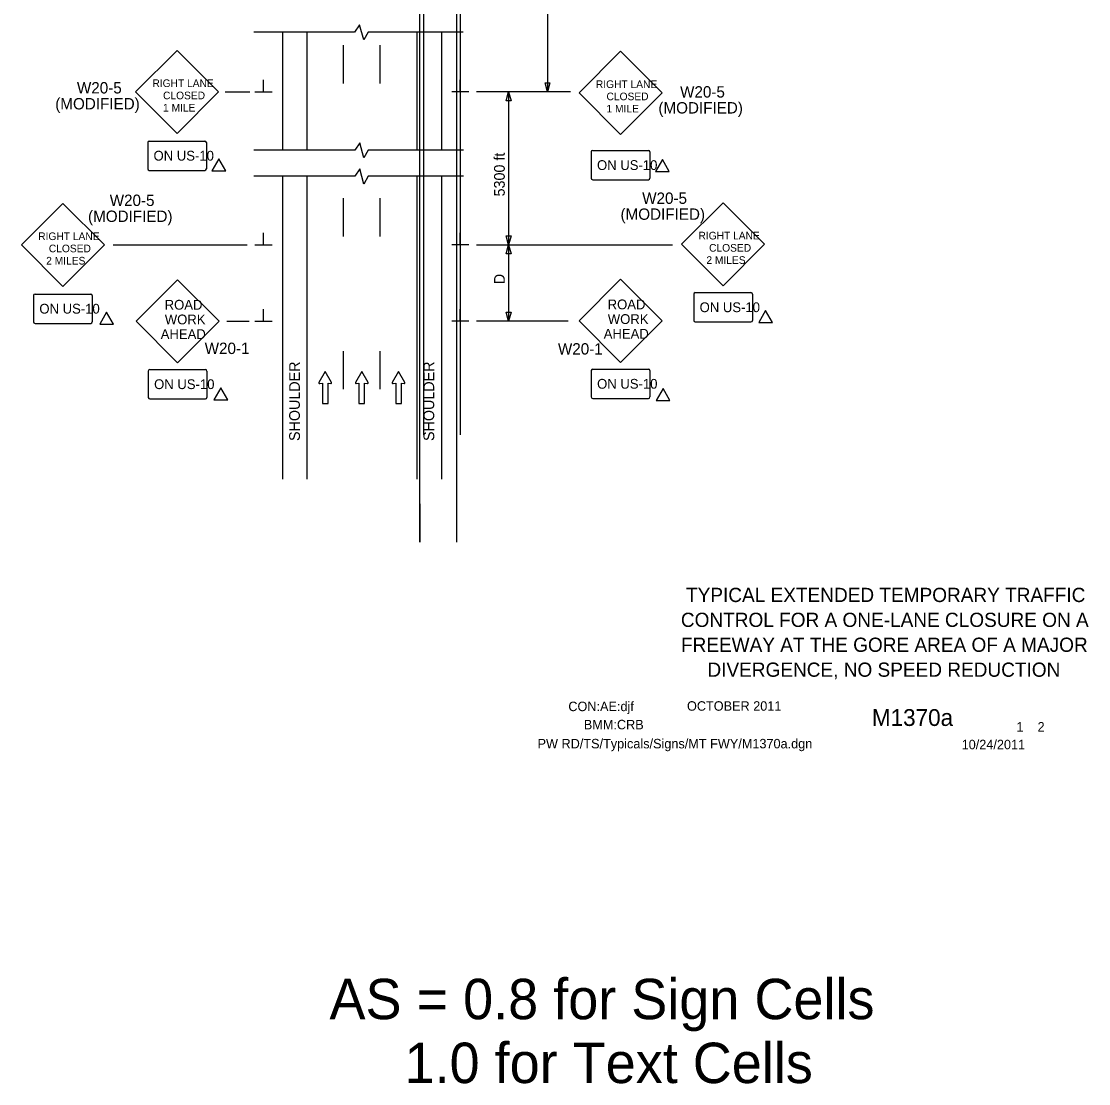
# Model space of a CAD drawing. Extents: x 16722 to 18475, y 7001 to 8243.
# Drawn here: x 16733 to 17431, y 7001 to 7696 of the extents above; entities that cross this region are included whole.
import ezdxf

# ---------------------------------------------------------------- set-up
doc = ezdxf.new("R2010")
doc.units = 0
for name, color, linetype in [('ALI_LEGAL_EX', 7, 'Continuous'), ('BORDER', 7, 'Continuous'), ('BORDER_SIGNAL_WO', 7, 'Continuous'), ('MT_SCRATCH_LEVEL_E', 7, 'Continuous'), ('PAVT_EDGE_EX', 7, 'Continuous'), ('TRAFFIC_SIGNS_PR', 7, 'Continuous'), ('TYPICAL_TEXT_DIMEN_PR', 7, 'Continuous')]:
    doc.layers.add(name, color=color, linetype=linetype)

msp = doc.modelspace()

# ---------------------------------------------------------------- linework, layer by layer
at = {"layer": 'ALI_LEGAL_EX'}
for p, q in [((16995.95, 8243.16), (16995.95, 7425.02)), ((17019.95, 8243.16), (17019.95, 7425.02)), ((16993.65, 7354.84), (16993.65, 7855.19)), ((17017.65, 7354.84), (17017.65, 7855.19))]:
    msp.add_line(p, q, dxfattribs=at)
for points in [[(16943.65, 7654.84), (16943.65, 7679.84)], [(16967.65, 7654.84), (16967.65, 7679.84)], [(16943.65, 7554.84), (16943.65, 7579.84)], [(16967.65, 7554.84), (16967.65, 7579.84)], [(16943.65, 7454.84), (16943.65, 7479.84)], [(16967.65, 7454.84), (16967.65, 7479.84)], [(16993.65, 7379.84), (16993.65, 7354.84)]]:
    msp.add_lwpolyline(points, dxfattribs=at)
at = {"layer": 'MT_SCRATCH_LEVEL_E'}
for p, q in [((16931.67, 7466.47), (16927.55, 7459.23)), ((16935.81, 7459.23), (16931.67, 7466.47)), ((16955.57, 7466.47), (16951.46, 7459.23)), ((16959.72, 7459.23), (16955.57, 7466.47)), ((16979.62, 7466.47), (16975.51, 7459.23)), ((16983.77, 7459.23), (16979.62, 7466.47)), ((16928.04, 7458.54), (16929.81, 7458.86)), ((16929.81, 7458.86), (16929.81, 7445.6)), ((16933.56, 7445.6), (16933.56, 7458.86)), ((16933.56, 7458.86), (16935.33, 7458.54)), ((16951.94, 7458.54), (16953.72, 7458.86)), ((16953.72, 7458.86), (16953.72, 7445.6)), ((16957.46, 7445.6), (16957.46, 7458.86)), ((16957.46, 7458.86), (16959.24, 7458.54)), ((16975.99, 7458.54), (16977.77, 7458.86)), ((16977.77, 7458.86), (16977.77, 7445.6)), ((16981.51, 7445.6), (16981.51, 7458.86)), ((16981.51, 7458.86), (16983.29, 7458.54)), ((16929.81, 7445.6), (16933.56, 7445.6)), ((16953.72, 7445.6), (16957.46, 7445.6)), ((16977.77, 7445.6), (16981.51, 7445.6))]:
    msp.add_line(p, q, dxfattribs=at)
for centre, start, end in [((16927.96, 7459), 150.42484, 279.96381), ((16935.4, 7459), 260.03619, 29.77312), ((16951.87, 7459), 150.42484, 279.96381), ((16959.31, 7459), 260.03619, 29.77312), ((16975.92, 7459), 150.42484, 279.96381), ((16983.36, 7459), 260.03619, 29.77312)]:
    msp.add_arc(centre, 0.463, start, end, dxfattribs=at)
at = {"layer": 'PAVT_EDGE_EX'}
for p, q in [((16903.65, 7688.48), (16903.65, 7611.33)), ((16919.65, 7688.48), (16919.65, 7611.33)), ((16991.65, 7688.48), (16991.65, 7611.33)), ((17007.65, 7688.48), (17007.65, 7611.33)), ((16903.65, 7594.19), (16903.65, 7396.13)), ((16919.65, 7594.19), (16919.65, 7396.13)), ((16991.65, 7594.19), (16991.65, 7396.13)), ((17007.65, 7594.19), (17007.65, 7396.13))]:
    msp.add_line(p, q, dxfattribs=at)
at = {"layer": 'TRAFFIC_SIGNS_PR'}
for p, q in [((16834.74, 7676.53), (16807.59, 7649.37)), ((16861.89, 7649.37), (16834.74, 7676.53)), ((17124.81, 7675.89), (17097.66, 7648.74)), ((17151.96, 7648.74), (17124.81, 7675.89)), ((16807.59, 7649.37), (16834.74, 7622.23)), ((16834.74, 7622.23), (16861.89, 7649.37)), ((17097.66, 7648.74), (17124.81, 7621.59)), ((17124.81, 7621.59), (17151.96, 7648.74)), ((16815.54, 7616.23), (16815.54, 7599.02)), ((16816.54, 7617.23), (16852.95, 7617.23)), ((16853.95, 7616.23), (16853.95, 7599.02)), ((17105.61, 7610.08), (17105.61, 7592.88)), ((17106.61, 7611.08), (17143.01, 7611.08)), ((17144.01, 7610.08), (17144.01, 7592.88)), ((16816.54, 7598.02), (16852.95, 7598.02)), ((17106.61, 7591.88), (17143.01, 7591.88)), ((16760.06, 7576.44), (16732.91, 7549.29)), ((16787.21, 7549.29), (16760.06, 7576.44)), ((17191.9, 7576.85), (17164.75, 7549.7)), ((17219.05, 7549.7), (17191.9, 7576.85)), ((16732.91, 7549.29), (16760.06, 7522.14)), ((16760.06, 7522.14), (16787.21, 7549.29)), ((17164.75, 7549.7), (17191.9, 7522.55)), ((17191.9, 7522.55), (17219.05, 7549.7)), ((16835.1, 7526.53), (16807.95, 7499.37)), ((16862.26, 7499.37), (16835.1, 7526.53)), ((17124.85, 7526.77), (17097.69, 7499.62)), ((17152.01, 7499.62), (17124.85, 7526.77)), ((16740.86, 7516.14), (16740.86, 7498.94)), ((16741.86, 7517.14), (16778.27, 7517.14)), ((16779.27, 7516.14), (16779.27, 7498.94)), ((17172.7, 7517.1), (17172.7, 7499.89)), ((17173.7, 7518.1), (17210.11, 7518.1)), ((17211.11, 7517.1), (17211.11, 7499.89)), ((16741.86, 7497.94), (16778.27, 7497.94)), ((16807.95, 7499.37), (16835.1, 7472.22)), ((16835.1, 7472.22), (16862.26, 7499.37)), ((17097.69, 7499.62), (17124.85, 7472.46)), ((17124.85, 7472.46), (17152.01, 7499.62)), ((17173.7, 7498.89), (17210.11, 7498.89)), ((16815.9, 7466.77), (16815.9, 7449.57)), ((16816.9, 7467.77), (16853.31, 7467.77)), ((16854.31, 7466.77), (16854.31, 7449.57)), ((17105.65, 7467.02), (17105.65, 7449.81)), ((17106.65, 7468.02), (17143.05, 7468.02)), ((17144.05, 7467.02), (17144.05, 7449.81)), ((17106.65, 7448.81), (17143.05, 7448.81)), ((16816.9, 7448.57), (16853.31, 7448.57))]:
    msp.add_line(p, q, dxfattribs=at)
for centre, start, end in [((16816.54, 7616.22), 90, 180), ((16852.95, 7616.22), 0, 90), ((17106.61, 7610.08), 90, 180), ((17143.01, 7610.08), 0, 90), ((16816.54, 7599.02), 180, 270), ((16852.95, 7599.02), 270, 0), ((17106.61, 7592.88), 180, 270), ((17143.01, 7592.88), 270, 0), ((16741.86, 7516.14), 90, 180), ((16778.26, 7516.14), 0, 90), ((17173.7, 7517.1), 90, 180), ((17210.11, 7517.1), 0, 90), ((16741.86, 7498.94), 180, 270), ((16778.26, 7498.94), 270, 0), ((17173.7, 7499.89), 180, 270), ((17210.11, 7499.89), 270, 0), ((16816.9, 7466.77), 90, 180), ((16853.31, 7466.77), 0, 90), ((17106.65, 7467.02), 90, 180), ((17143.05, 7467.02), 0, 90), ((16816.9, 7449.57), 180, 270), ((16853.31, 7449.57), 270, 0), ((17106.65, 7449.81), 180, 270), ((17143.05, 7449.81), 270, 0)]:
    msp.add_arc(centre, 1, start, end, dxfattribs=at)
at = {"layer": 'TYPICAL_TEXT_DIMEN_PR'}
for p, q in [((17077.09, 7949.37), (17077.09, 7649.37)), ((16954.16, 7693.27), (16950.91, 7688.47)), ((16956.9, 7683.33), (16954.16, 7693.27)), ((16950.91, 7688.47), (16884.97, 7688.47)), ((16959.65, 7688.47), (16956.9, 7683.33)), ((17021.98, 7688.47), (16959.65, 7688.47)), ((16891.27, 7649.37), (16891.27, 7657.16)), ((17020.02, 7649.37), (17020.02, 7657.16)), ((17077.09, 7649.37), (17075.52, 7655.24)), ((17075.52, 7655.24), (17077.09, 7655.24)), ((17077.09, 7655.24), (17078.66, 7655.24)), ((17078.66, 7655.24), (17077.09, 7649.37)), ((16866.22, 7649.37), (16882.34, 7649.37)), ((16885.65, 7649.37), (16896.9, 7649.37)), ((17025.65, 7649.37), (17014.4, 7649.37)), ((17092.09, 7649.37), (17030.65, 7649.37)), ((17050.08, 7643.51), (17051.65, 7649.37)), ((17051.65, 7649.37), (17051.65, 7549.37)), ((17051.65, 7649.37), (17053.22, 7643.51)), ((17051.65, 7643.51), (17050.08, 7643.51)), ((17053.22, 7643.51), (17051.65, 7643.51)), ((16951, 7611.31), (16885.06, 7611.31)), ((16954.25, 7616.11), (16951, 7611.31)), ((16956.99, 7606.17), (16954.25, 7616.11)), ((16959.74, 7611.31), (16956.99, 7606.17)), ((17022.07, 7611.31), (16959.74, 7611.31)), ((16954.25, 7598.98), (16951, 7594.18)), ((16956.99, 7589.04), (16954.25, 7598.98)), ((16951, 7594.18), (16885.06, 7594.18)), ((16959.74, 7594.18), (16956.99, 7589.04)), ((17022.07, 7594.18), (16959.74, 7594.18)), ((16891.27, 7549.37), (16891.27, 7557.16)), ((17020.02, 7549.37), (17020.02, 7557.16)), ((17051.65, 7549.37), (17050.08, 7555.24)), ((17050.08, 7555.24), (17051.65, 7555.24)), ((17051.65, 7555.24), (17053.22, 7555.24)), ((17053.22, 7555.24), (17051.65, 7549.37)), ((16792.96, 7549.37), (16880.65, 7549.37)), ((16885.65, 7549.37), (16896.9, 7549.37)), ((17025.65, 7549.37), (17014.4, 7549.37)), ((17030.65, 7549.37), (17158.84, 7549.37)), ((17050.08, 7543.51), (17051.65, 7549.37)), ((17051.65, 7549.37), (17051.65, 7499.37)), ((17051.65, 7549.37), (17053.22, 7543.51)), ((17051.65, 7543.51), (17050.08, 7543.51)), ((17053.22, 7543.51), (17051.65, 7543.51)), ((16891.27, 7499.37), (16891.27, 7507.16)), ((17020.02, 7499.37), (17020.02, 7507.16)), ((17051.65, 7499.37), (17050.08, 7505.24)), ((17050.08, 7505.24), (17051.65, 7505.24)), ((17051.65, 7505.24), (17053.22, 7505.24)), ((17053.22, 7505.24), (17051.65, 7499.37)), ((16867.26, 7499.37), (16881.95, 7499.37)), ((16885.65, 7499.37), (16896.9, 7499.37)), ((17025.65, 7499.37), (17014.4, 7499.37)), ((17090.66, 7499.37), (17030.65, 7499.37))]:
    msp.add_line(p, q, dxfattribs=at)
for points in [[(16862.09, 7605.67), (16857.57, 7597.83), (16866.62, 7597.83)], [(17152.16, 7605.03), (17147.64, 7597.19), (17156.69, 7597.19)], [(16788.67, 7505.28), (16784.14, 7497.44), (16793.19, 7497.44)], [(17219.7, 7506.36), (17215.18, 7498.52), (17224.23, 7498.52)], [(16863.36, 7455.78), (16858.83, 7447.94), (16867.88, 7447.94)], [(17152.65, 7455.32), (17148.12, 7447.48), (17157.17, 7447.48)]]:
    msp.add_lwpolyline(points, close=True, dxfattribs=at)

# ---------------------------------------------------------------- texts
at = {"layer": 'BORDER'}
for s, p in [('TYPICAL EXTENDED TEMPORARY TRAFFIC', (17167.67, 7315.69)), ('CONTROL FOR A ONE-LANE CLOSURE ON A', (17164.29, 7299.39)), ('FREEWAY AT THE GORE AREA OF A MAJOR', (17164.34, 7283.09)), ('DIVERGENCE, NO SPEED REDUCTION', (17181.67, 7266.79))]:
    msp.add_text(s, height=9.3, dxfattribs=at).set_placement(p)
at = {"layer": 'BORDER_SIGNAL_WO'}
for s, height, p in [('CON:AE:djf  ', 6.2, (17090.69, 7244.31)), ('    OCTOBER 2011    ', 6.2, (17159.08, 7244.59)), ('    M1370a   ', 11, (17272.86, 7234.63)), ('BMM:CRB   ', 6.2, (17100.81, 7232.42)), (' 1    2 ', 6.2, (17381.45, 7230.95)), ('PW RD/TS/Typicals/Signs/MT FWY/M1370a.dgn      ', 6.2, (17070.55, 7219.96)), ('10/24/2011    ', 6.2, (17347.93, 7219.38)), ('AS = 0.8 for Sign Cells', 26.4241, (16934.45, 7042.82)), ('     1.0 for Text Cells', 26.4241, (16934.45, 7001.03))]:
    msp.add_text(s, height=height, dxfattribs=at).set_placement(p)
at = {"layer": 'TRAFFIC_SIGNS_PR'}
for s, height, p in [('W20-5', 7.439, (16769.27, 7648.32)), ('RIGHT LANE', 4.999, (16818.63, 7652.53)), ('RIGHT LANE', 4.999, (17108.69, 7651.89)), ('W20-5', 7.439, (17163.77, 7645.66)), ('(MODIFIED)', 7.439, (16755.09, 7637.89)), ('CLOSED', 4.999, (16825.58, 7644.53)), ('CLOSED', 4.999, (17115.65, 7643.89)), ('1 MILE', 4.999, (16825.57, 7636.53)), ('1 MILE', 4.999, (17115.64, 7635.89)), ('(MODIFIED)', 7.439, (17149.59, 7635.22)), ('ON US-10', 6.401, (16819.38, 7604.42)), ('ON US-10', 6.401, (17109.44, 7598.28)), ('W20-5', 7.439, (16790.71, 7574.72)), ('W20-5', 7.439, (17138.99, 7576.12)), ('(MODIFIED)', 7.439, (16776.53, 7564.28)), ('(MODIFIED)', 7.439, (17124.81, 7565.68)), ('RIGHT LANE', 4.999, (16743.94, 7552.44)), ('RIGHT LANE', 4.999, (17175.78, 7552.85)), ('CLOSED', 4.999, (16750.9, 7544.44)), ('CLOSED', 4.999, (17182.74, 7544.85)), ('2 MILES', 4.999, (16749.15, 7536.44)), ('2 MILES', 4.999, (17180.99, 7536.85)), ('ROAD', 6.401, (16826.64, 7506.91)), ('ROAD', 6.401, (17116.39, 7507.15)), ('ON US-10', 6.401, (17176.54, 7505.29)), ('ON US-10', 6.401, (16744.7, 7504.34)), ('WORK', 6.401, (16826.75, 7497.31)), ('WORK', 6.401, (17116.5, 7497.55)), ('AHEAD', 6.401, (16824.06, 7487.71)), ('AHEAD', 6.401, (17113.81, 7487.95)), ('W20-1', 7.441, (16852.82, 7477.9)), ('W20-1', 7.441, (17083.87, 7477.56)), ('ON US-10', 6.401, (16819.74, 7454.97)), ('ON US-10', 6.401, (17109.49, 7455.22))]:
    msp.add_text(s, height=height, dxfattribs=at).set_placement(p)
at = {"layer": 'TYPICAL_TEXT_DIMEN_PR'}
for s, p in [('5300 ft', (17049.09, 7580.98)), ('D', (17049.09, 7523.59)), ('SHOULDER', (16915.09, 7421.01)), ('SHOULDER', (17002.95, 7421.01))]:
    msp.add_text(s, height=7, rotation=90, dxfattribs=at).set_placement(p)

doc.saveas('drawing.dxf')
